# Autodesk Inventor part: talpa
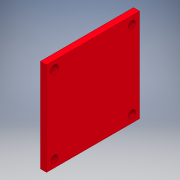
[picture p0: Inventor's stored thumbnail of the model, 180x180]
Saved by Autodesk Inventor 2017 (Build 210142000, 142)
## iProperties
Created: 2017-11
Part Number: talpa
Material: Generic
Document SubType Name: Modeling
Designer: iusti
Density: 1 g/cm^3
Appearance: Default
Mass: 1764.05 g
Surface Area: 2064.07 cm^2
Volume: 1764.05 cm^3
Author: iusti
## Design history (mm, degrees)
sketch "Sketch1"
  geometry: L1 (150, 150)-(-150, 150); L2 (-150, 150)-(-150, -150); L3 (-150, -150)-(150, -150); L4 (150, -150)-(150, 150); C1 r 11.55 at (125, 125); C2 r 11.969 at (125, -125); C3 r 11.188 at (-125, -125); C4 r 13.05 at (-125, 125); 1 further point
  constraints: 8 end point, 4 centre point, 2 parallel, 1 horizontal, 1 perpendicular
  dimensions: "d0" = 300 distance of L3.end L1.start; "d1" = 300 distance of L2.end L3.end; "d2" = 250 distance of C2.centre C1.centre; "d3" = 250 distance of C4.centre C1.centre; "d4" = 250 distance of C3.centre C2.centre (= d3); "d5" = 250 distance of C3.centre C4.centre (= d2); "d6" = 25 distance from line of L1 C1.centre; "d7" = 25 distance from line of L4 C1.centre; "d8" = 25 distance from line of L3 C3.centre; "d9" = 25 distance from line of L2 C3.centre
extrude "Extrusion1" new body sketch "Sketch1" distance "d10" = 20; taper "d11" = 0 deg
body "Solid1"
